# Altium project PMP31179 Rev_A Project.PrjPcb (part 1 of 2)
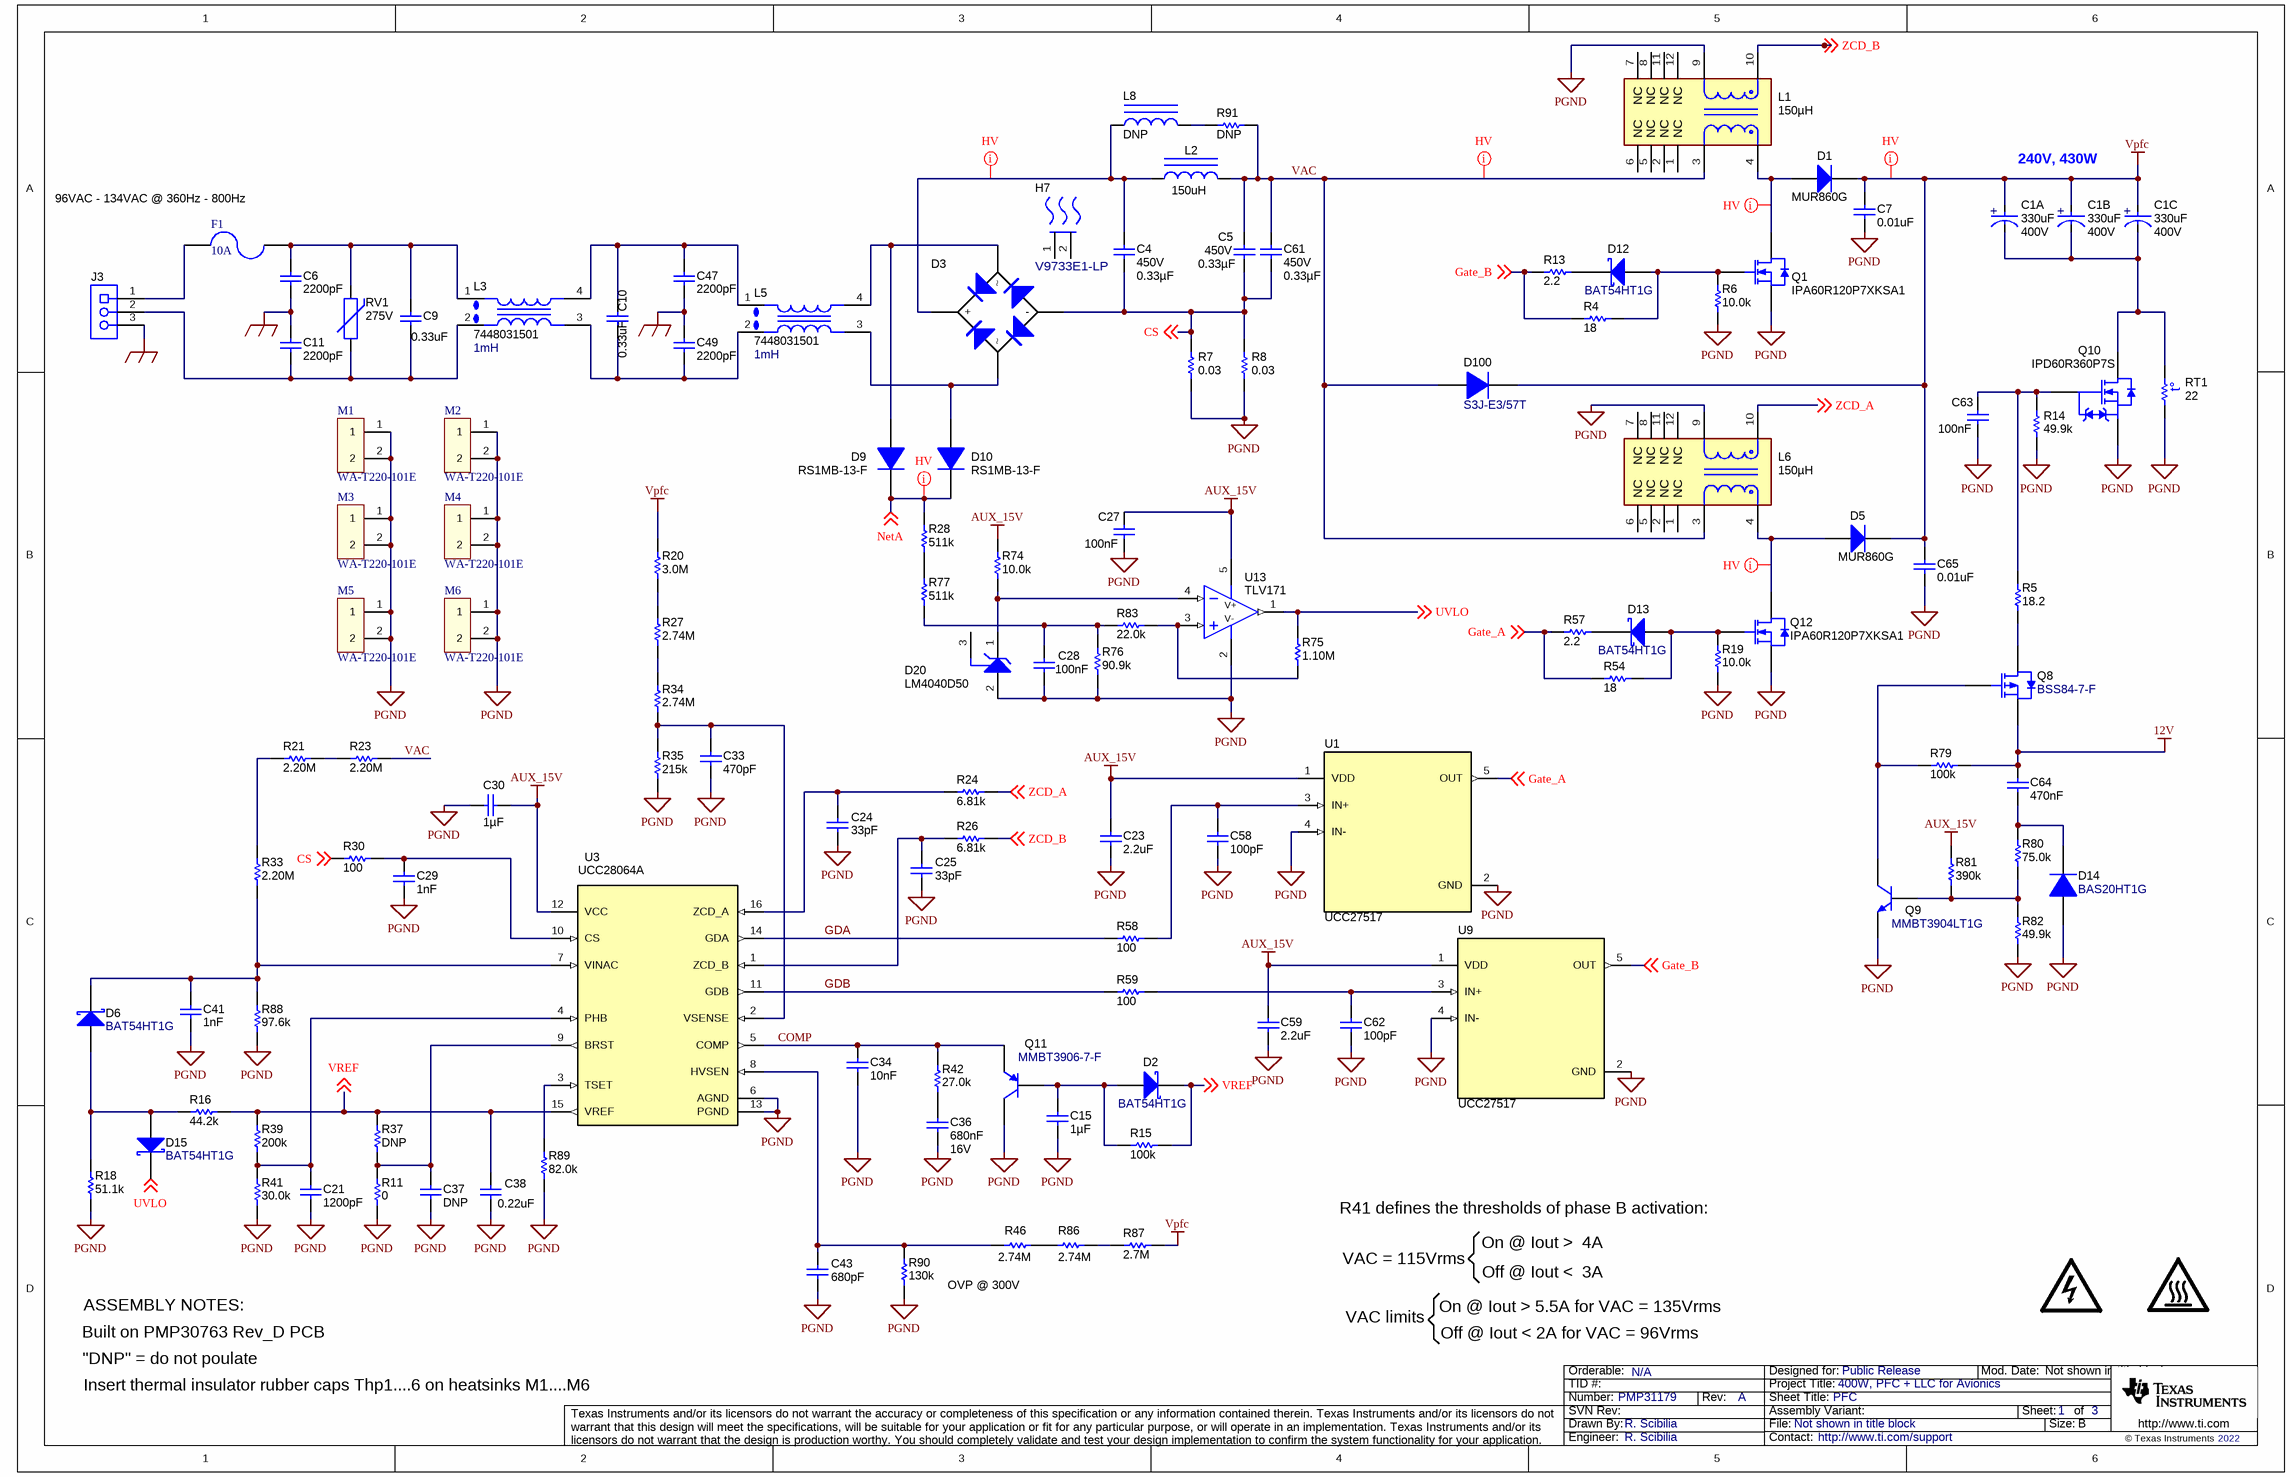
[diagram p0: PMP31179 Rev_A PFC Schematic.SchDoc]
TechSupport: http://www.ti.com/support; SCH_Rev: A; PRJ_Title: 400W, PFC + LLC for Avionics; PRJ_Number: PMP31179; PRJ_Engineer: R. Scibilia; PRJ_Customer: Public Release; PCB_Rev: D; PCB_Layout: PMP30763; EVM_orderable: N/A; CopyrightYear: 2022
3 sheets, 259 parts. Net scope: global (net labels, ports and power ports of the same name join across sheets).
Board file: PMP31179 Rev_A_board.PcbDoc
Sheets:
  PMP31179 Rev_A PFC Schematic.SchDoc
  PMP31179 Rev_A LLC Schematic.SchDoc
  PMP31179 Rev_A Hardware.SchDoc

## Sheet PMP31179 Rev_A PFC Schematic.SchDoc: PFC
size 431 x 279 mm; Date: Not shown in title block; ApprovedBy: Not shown in title block; CheckedBy: Not shown in title block; Author: Not shown in title block; CompanyName: Not shown in title block; DrawnBy: R. Scibilia; Engineer: R. Scibilia; Organization: Not shown in title block; Address1: Not shown in title block; Address2: Not shown in title block; Address3: Not shown in title block; Address4: Not shown in title block; DocumentNumber: 1; Revision: Use project parameter SCH_Rev; SheetNumber: 1; SheetTotal: 3; PageSetup: Record=PageOptions¦CenterHorizontal=True¦CenterVertical=True¦PrintScale=1.00¦XCorrection=1.00¦YCorrection=1.00¦PrintKind=0¦BorderSize=5000000¦LeftOffset=0¦BottomOffset=0¦Orientation=2¦PaperLength=1000¦PaperWidth=1000¦Scale=100¦PaperSource=15¦PrintQuality=600¦MediaType=1¦DitherType=10¦PaperKind=Letter¦PrintScaleMode=1

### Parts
(Parts that share a designator on the sheet are numbered #1, #2 ... from top to bottom, then left to right.)
C1A  VDC_V: 400V  ValueDisplayed: 330uF  [FP-ESMR451VSN221MR25S_RADIAL-MFG]  (hidden comment: 861011385023)
C1B  VDC_V: 400V  ValueDisplayed: 330uF  [FP-ESMR451VSN221MR25S_RADIAL-MFG]  (hidden comment: 861011385023)
C1C  VDC_V: 400V  ValueDisplayed: 330uF  [FP-ESMR451VSN221MR25S_RADIAL-MFG]  (hidden comment: 861011385023)
C4  VDC_V: 450V  ValueDisplayed: 0.33µF  [R46_1300x1200x600]  (hidden comment: ECW-FE2W334K)
C5  VDC_V: 450V  ValueDisplayed: 0.33µF  [R46_1300x1200x600]  (hidden comment: ECW-FE2W334K)
C6  ValueDisplayed: 2200pF  [AY2_950x500_Straight]  (hidden comment: Capacitor)
C7  ValueDisplayed: 0.01uF  [1210]  (hidden comment: 885342208009)
C9  ValueDisplayed: 0.33uF  [B32922_14.5mm]  (hidden comment: Capacitor)
C10  ValueDisplayed: 0.33uF  [B32922_14.5mm]  (hidden comment: Capacitor)
C11  ValueDisplayed: 2200pF  [AY2_950x500_Straight]  (hidden comment: Capacitor)
C15  Cap_F: 1µF  [0603]  (hidden comment: 885012206076)
C21  value 1200pF  [0603]  (hidden comment: GRM1885C1H122JA01D)
C23  value 2.2uF  [0805_150]  (hidden comment: 885012207079)
C24  ValueDisplayed: 33pF  [0603]  (hidden comment: 885012006054)
C25  ValueDisplayed: 33pF  [0603]  (hidden comment: 885012006054)
C27  Cap_F: 100nF  [0603]  (hidden comment: 885012206095)
C28  Cap_F: 100nF  [0603]  (hidden comment: 885012206095)
C29  Cap_F: 1nF  [0603]  (hidden comment: 885012206083)
C30  Cap_F: 1µF  [0603]  (hidden comment: 885012206076)
C33  ValueDisplayed: 470pF  [0603]  (hidden comment: 885012006061)
C34  Cap_F: 10nF  [0603]  (hidden comment: 885012206040)
C36  Cap_F: 680nF  VDC_V: 16V  [0603]  (hidden comment: CL10B684KO8NFNC)
C37  DNP  [0603]
C38  ValueDisplayed: 0.22uF  [0603]  (hidden comment: GRM188R71H224KAC4D)
C41  Cap_F: 1nF  [0603]  (hidden comment: 885012206108)
C43  ValueDisplayed: 680pF  [0603]  (hidden comment: Capacitor)
C47  ValueDisplayed: 2200pF  [AY2_950x500_Straight]  (hidden comment: Capacitor)
C49  ValueDisplayed: 2200pF  [AY2_950x500_Straight]  (hidden comment: Capacitor)
C58  ValueDisplayed: 100pF  [0603]  (hidden comment: 885012006057)
C59  value 2.2uF  [0805_150]  (hidden comment: 885012207079)
C61  VDC_V: 450V  ValueDisplayed: 0.33µF  [R46_1300x1200x600]  (hidden comment: ECW-FE2W334K)
C62  ValueDisplayed: 100pF  [0603]  (hidden comment: 885012006057)
C63  Cap_F: 100nF  [0603]  (hidden comment: 885012206095)
C64  Cap_F: 470nF  [0805_HV]  (hidden comment: 885012207102)
C65  ValueDisplayed: 0.01uF  [1210]  (hidden comment: 885342208009)
D1  MUR860G  [TO-220AC]
D2  BAT54HT1G  [SOD-323]
D3  GBU2510-G  [GBU]  (value not drawn)
D5  MUR860G  [TO-220AC]
D6  BAT54HT1G  [SOD-323]
D9  Value1: RS1MB-13-F  [SMB]  (hidden comment: DIODE)
D10  Value1: RS1MB-13-F  [SMB]  (hidden comment: DIODE)
D12  BAT54HT1G  [SOD-323]
D13  BAT54HT1G  [SOD-323]
D14  BAS20HT1G  [SOD-323]
D15  BAT54HT1G  [SOD-323]
D20  value LM4040D50  [DBZ0003A_N]  (hidden comment: LM4040D50QDBZR)
D100  S3J-E3/57T  [SMC]
F1  value 10A  [FUSE_38321000000]  (hidden comment: 38321000000)
H7  V9733E1-LP  [FP-V9733E1-LP_THERMAL_HEATSINK_25MM0_42MM0-MFG]
J3  691213510003  [On-Shore_ED120_3DS]  (value not drawn)
L1  value 150µH  [FP-750318973r00_PTH_30MM35_29MM2-MFG]  (hidden comment: 750318973r00)
L2  ValueDisplayed: 150uH  [WE-FI_2750x1300]  (hidden comment: 7447076)
L3  7448031501  value 1mH  [WURTH_7448031501]
L5  7448031501  value 1mH  [WURTH_7448031501]
L6  value 150µH  [FP-750318973r00_PTH_30MM35_29MM2-MFG]  (hidden comment: 750318973r00)
L8  DNP  [WE-PD4-S]
LOGO?#1  DANGER HIGH VOLTAGE  [IEC_HighVoltage_Small]  (value not drawn)  (graphical)
LOGO?#2  CAUTION HOT SURFACE  [IEC_HotSurface_Small]  (value not drawn)  (graphical)
M1  WA-T220-101E  [HEATSINK_WA-T220-101E]
M2  WA-T220-101E  [HEATSINK_WA-T220-101E]
M3  WA-T220-101E  [HEATSINK_WA-T220-101E]
M4  WA-T220-101E  [HEATSINK_WA-T220-101E]
M5  WA-T220-101E  [HEATSINK_WA-T220-101E]
M6  WA-T220-101E  [HEATSINK_WA-T220-101E]
Q1  IPA60R120P7XKSA1  [TO-220AB]
Q8  BSS84-7-F  [SOT-23]
Q9  MMBT3904LT1G  [SOT-23]
Q10  value IPD60R360P7S  [DPAK]  (hidden comment: IPD60R360P7SAUMA1)
Q11  MMBT3906-7-F  [SOT-23]
Q12  IPA60R120P7XKSA1  [TO-220AB]
R4  ValueDisplayed: 18  [0805_HV]  (hidden comment: ERJ-6GEYJ180V)
R5  ValueDisplayed: 18.2  [0805_HV1]  (hidden comment: Resistor)
R6  ValueDisplayed: 10.0k  [0805_HV]  (hidden comment: Resistor)
R7  ValueDisplayed: 0.03  [2512]  (hidden comment: Resistor)
R8  ValueDisplayed: 0.03  [2512]  (hidden comment: Resistor)
R11  ValueDisplayed: 0  [0603]  (hidden comment: RMCF0603ZT0R00)
R13  ValueDisplayed: 2.2  [0805_HV]  (hidden comment: RC0805JR-072R2L)
R14  ValueDisplayed: 49.9k  [0603]  (hidden comment: ERJ-3EKF4992V)
R15  ValueDisplayed: 100k  [0603]  (hidden comment: CRCW0603100KFKEA)
R16  ValueDisplayed: 44.2k  [0603]  (hidden comment: RC0603FR-0744K2L)
R18  ValueDisplayed: 51.1k  [0603]  (hidden comment: CRCW060351K1FKEA)
R19  ValueDisplayed: 10.0k  [0805_HV]  (hidden comment: Resistor)
R20  ValueDisplayed: 3.0M  [1206]  (hidden comment: CRCW12063M00JNEA)
R21  ValueDisplayed: 2.20M  [0805_HV]  (hidden comment: RC0805FR-072M2L)
R23  ValueDisplayed: 2.20M  [0805_HV]  (hidden comment: RC0805FR-072M2L)
R24  ValueDisplayed: 6.81k  [0603]  (hidden comment: CRCW06036K81FKEA)
R26  ValueDisplayed: 6.81k  [0603]  (hidden comment: CRCW06036K81FKEA)
R27  ValueDisplayed: 2.74M  [0805_HV]  (hidden comment: Resistor)
R28  value 511k  [1206]  (hidden comment: Resistor)
R30  ValueDisplayed: 100  [0603]  (hidden comment: Resistor)
R33  ValueDisplayed: 2.20M  [0805_HV]  (hidden comment: RC0805FR-072M2L)
R34  ValueDisplayed: 2.74M  [0805_HV]  (hidden comment: Resistor)
R35  ValueDisplayed: 215k  [0603]  (hidden comment: RT0603DRE07215KL)
R37  DNP  [0603]
R39  ValueDisplayed: 200k  [0603]  (hidden comment: RC0603FR-07200KL)
R41  ValueDisplayed: 30.0k  [0603]  (hidden comment: ERJ-3EKF3002V)
R42  ValueDisplayed: 27.0k  [0603]  (hidden comment: RC0603FR-0727KL)
R46  ValueDisplayed: 2.74M  [0805_HV]  (hidden comment: Resistor)
R54  ValueDisplayed: 18  [0805_HV]  (hidden comment: ERJ-6GEYJ180V)
R57  ValueDisplayed: 2.2  [0805_HV]  (hidden comment: RC0805JR-072R2L)
R58  ValueDisplayed: 100  [0603]  (hidden comment: ERJ-3EKF1000V)
R59  ValueDisplayed: 100  [0603]  (hidden comment: ERJ-3EKF1000V)
R74  ValueDisplayed: 10.0k  [0805_HV]  (hidden comment: Resistor)
R75  ValueDisplayed: 1.10M  [0603]  (hidden comment: CRCW06031M10FKEA)
R76  ValueDisplayed: 90.9k  [0603]  (hidden comment: CRCW060390K9FKEA)
R77  value 511k  [1206]  (hidden comment: Resistor)
R79  ValueDisplayed: 100k  [0603]  (hidden comment: CRCW0603100KFKEA)
R80  ValueDisplayed: 75.0k  [0603]  (hidden comment: RC0603FR-0775KL)
R81  ValueDisplayed: 390k  [0603]  (hidden comment: CRCW0603390KJNEA)
R82  ValueDisplayed: 49.9k  [0603]  (hidden comment: RC0603FR-0749K9L)
R83  ValueDisplayed: 22.0k  [0603]  (hidden comment: ERJ-3EKF2202V)
R86  ValueDisplayed: 2.74M  [0805_HV]  (hidden comment: Resistor)
R87  ValueDisplayed: 2.7M  [1206]  (hidden comment: CRCW12062M70JNEA)
R88  ValueDisplayed: 97.6k  [0603]  (hidden comment: CRCW060397K6FKEA)
R89  ValueDisplayed: 82.0k  [0603]  (hidden comment: RC0603FR-0782KL)
R90  ValueDisplayed: 130k  [0603]  (hidden comment: CRCW0603130KFKEA)
R91  DNP  [2512]
RT1  value 22  [S237]  (hidden comment: B57237S0220M000)
RV1  value 275V  [VAR_S10K275E2]  (hidden comment: Varistor_MetalOxide)
U1  value UCC27517  [DBV0005A_N]  (hidden comment: UCC27517DBVR)
U3  value UCC28064A  [D0016A_N]  (hidden comment: UCC28064ADR)
U9  value UCC27517  [DBV0005A_N]  (hidden comment: UCC27517DBVR)
U13  value TLV171  [DBV0005A_N]  (hidden comment: TLV171IDBVR)

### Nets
12V: C64.1 Q8.2(S) R79.1
AUX_15V: C23.1 C27.1 C30.1 C59.1 R74.2 R81.2 U1.1(VDD) U3.12(VCC) U9.1(VDD) U13.5(V+)
EARTH: C6.2 C11.1 C47.2 C49.1 J3.3
PGND: C7.2 C15.2 C21.2 C23.2 C24.2 C25.2 C27.2 C28.2 C29.2 C30.2 C33.2 C34.2 C36.2 C37.2 C38.2 C41.2 C43.2 C58.2 C59.2 C62.2 C63.2 C65.2 D14.2(A) D20.2(ANODE) L1.9 L6.9 M1.1 M1.2 M2.1 M2.2 M3.1 M3.2 M4.1 M4.2 M5.1 M5.2 M6.1 M6.2 Q1.3(S) Q9.2(E) Q10.3(S) Q11.3(C) Q12.3(S) R6.1 R7.1 R8.1 R11.1 R14.2 R18.1 R19.1 R35.1 R41.1 R76.1 R82.1 R88.2 R89.1 R90.1 RT1.1 U1.2(GND) U1.4(IN-) U3.6(AGND) U3.13(PGND) U9.2(GND) U9.4(IN-) U13.2(V-)
Vpfc: C1A.2(ANODE) C1B.2(ANODE) C1C.2(ANODE) C7.1 C65.1 D1.1(K) D5.1(K) D100.1(K) R20.2 R87.2
COMP: C34.1 Q11.2(E) R42.1 U3.5(COMP)
CS: C4.2 C5.2 C61.2 D3.4(-) R7.2 R8.2 R30.1 ; off-sheet CS
Gate_A: R54.1 R57.1 U1.5(OUT) ; off-sheet Gate_A
Gate_B: R4.1 R13.1 U9.5(OUT) ; off-sheet Gate_B
GDA: R58.1 U3.14(GDA)
GDB: R59.2 U3.11(GDB)
NetA: D9.1(K) D10.1(K) R28.1 ; off-sheet NetA
UVLO: D15.1(K) R75.2 U13.1(OUT) ; off-sheet UVLO
VAC: C5.1 C61.1 D100.2(A) L1.3 L2.2 L6.3 R23.2 R91.2
VREF: C38.1 D2.1(K) R15.1 R16.2 R37.2 R39.2 U3.15(VREF) ; off-sheet VREF
ZCD_A: L6.10 R24.2 ; off-sheet ZCD_A
ZCD_B: L1.10 R26.2 ; off-sheet ZCD_B
NetC1A_1: C1A.1(CATHODE) C1B.1(CATHODE) C1C.1(CATHODE) Q10.2(D) RT1.2
NetC4_1: C4.1 D3.1(+) L2.1 L8.1
NetC6_1: C6.1 C9.1 F1.2 L3.1 RV1.2
NetC9_2: C9.2 C11.2 J3.2 L3.2 RV1.1
NetC10_1: C10.1 C47.1 L3.4 L5.1
NetC10_2: C10.2 C49.2 L3.3 L5.2
NetC15_1: C15.1 D2.2(A) Q11.1(B) R15.2
NetC21_1: C21.1 R39.1 R41.2 U3.4(PHB)
NetC24_1: C24.1 R24.1 U3.16(ZCD_A)
NetC25_1: C25.1 R26.1 U3.1(ZCD_B)
NetC28_1: C28.1 R76.2 R77.2 R83.1
NetC29_1: C29.1 R30.2 U3.10(CS)
NetC33_1: C33.1 R34.1 R35.2 U3.2(VSENSE)
NetC36_1: C36.1 R42.2
NetC37_1: C37.1 R11.2 R37.1 U3.9(BRST)
NetC41_1: C41.1 D6.1(K) R33.2 R88.1 U3.7(VINAC)
NetC43_1: C43.1 R46.1 R90.2 U3.8(HVSEN)
NetC58_1: C58.1 R58.2 U1.3(IN+)
NetC62_1: C62.1 R59.1 U9.3(IN+)
NetC63_1: C63.1 Q10.1(G) R5.1 R14.1
NetC64_2: C64.2 D14.1(K) R80.2
NetD1_3: D1.3(A) L1.4 Q1.2(D)
NetD3_2: D3.2 D9.2(A) L5.4
NetD3_3: D3.3 D10.2(A) L5.3
NetD5_3: D5.3(A) L6.4 Q12.2(D)
NetD6_2: D6.2(A) D15.2(A) R16.1 R18.2
NetD12_1: D12.1(K) R13.2
NetD12_2: D12.2(A) Q1.1(G) R4.2 R6.2
NetD13_1: D13.1(K) R57.2
NetD13_2: D13.2(A) Q12.1(G) R19.2 R54.2
NetD20_1: D20.1(CATHODE) R74.1 U13.4(IN-)
NetF1_1: F1.1 J3.1
NetL8_2: L8.2 R91.1
NetQ8_1: Q8.1(G) Q9.3(C) R79.2
NetQ8_3: Q8.3(D) R5.2
NetQ9_1: Q9.1(B) R80.1 R81.1 R82.2
NetR20_1: R20.1 R27.2
NetR21_1: R21.1 R33.1
NetR21_2: R21.2 R23.1
NetR27_1: R27.1 R34.2
NetR28_2: R28.2 R77.1
NetR46_2: R46.2 R86.1
NetR75_1: R75.1 R83.2 U13.3(IN+)
NetR86_2: R86.2 R87.1
NetR89_2: R89.2 U3.3(TSET)

Not connected (* = marked no-connect by the designer): D20 3(NC); H7 1(MNT_1) 2(MNT_2); L1 1(NC) 2(NC) 5(NC) 6(NC) 7(NC) 8(NC) 11(NC) 12(NC); L6 1(NC) 2(NC) 5(NC) 6(NC) 7(NC) 8(NC) 11(NC) 12(NC)

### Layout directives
net class HV: NetA, NetC4_1, NetD1_3, NetD5_3, VAC, Vpfc

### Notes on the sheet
- 240V, 430W
- (near F1) 96VAC - 134VAC @ 360Hz - 800Hz
- R41 defines the thresholds of phase B activation:
- OVP @ 300V
- VAC = 115Vrms
- On @ Iout >  4A
- Off @ Iout <  3A
- ASSEMBLY NOTES:
- "DNP" = do not poulate
- Built on PMP30763 Rev_D PCB
- VAC limits
- Off @ Iout < 2A for VAC = 96Vrms
- On @ Iout > 5.5A for VAC = 135Vrms
- Insert thermal insulator rubber caps Thp1....6 on heatsinks M1....M6

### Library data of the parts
C1A C1B C1C = CMP-in_PMP30763: 330µF 400V Aluminum Electrolytic Capacitors Radial, Can - Snap-In  2000 Hrs @ 85°C; Manufacturer: Wuerth; SizeZ_mm: 30mm; Tolerance_%: 20%; Leakage Current: 920uA; Life: 2000Hours; AEC Qualified: No; IRMS_A: 2A
C4 C5 C61 = CMP-0012558-3: 0.33µF Film Capacitor 450V Polypropylene (PP), Metallized Radial; Manufacturer: Panasonic Electronic Components; TaMin_C: -40°C; Polarized: N; SizeAreaWB_mm2: 120; Value1: Unknown; TaMax_C: 110°C; Tolerance_%: 10%; SizeZ_mm: 12.1; SizeX_mm: 13; SizeY_mm: 6; Cap_Case: 13x12x6; SizeArea_mm2: 78; AEC Category: Q200
C6 C11 C47 C49 = CMP-0009587-2: CAP, CERM, 2200 pF, 300 V, +/- 20%, Y5U, AEC-Q200 Grade 1, D9.5xT5mm; PartNumber: AY2222M35Y5US63L7; Manufacturer: Vishay-Bccomponents; Polarized: N; Value: 2200pF; U/M: EA; Cap_F: 2.2nF; Value1: Unknown; VDC_V: 300V; TaMin_C: -55°C; TaMax_C: 125°C; Cap_Case: 9.5x5mm; SizeArea_mm2: 47.5; SizeAreaWB_mm2: 80.5; SizeX_mm: 9.5; SizeY_mm: 5; SizeZ_mm: 14.5; AEC Category: Q200; AEC Qualified: Y; AEC Grade: 1
C7 C65 = CMP-0009273-2: CAP, CERM, 0.01 uF, 500 V, +/- 10%, X7R, 1206; Manufacturer: Wuerth; TaMin_C: -55°C; Polarized: N; SizeAreaWB_mm2: 14.7; Value1: Unknown; U/M: EA; Value: 0.01uF; TaMax_C: 125°C; SizeZ_mm: 1.35; SizeX_mm: 3.2; SizeY_mm: 2.5; Cap_Case: 1206; Value2: 500V; SizeArea_mm2: 8; Cap_F: 10nF; AEC Category: Q200
C9 C10 = CMP-0012409-3: CAP, Film, 0.33 uF, 630 V, +/- 10%, TH; PartNumber: B32922C3334K; Manufacturer: TDK; Polarized: N; Value: 0.33uF; Cap_F: 330nF; Value1: Unknown; VDC_V: 630V; TaMin_C: -40°C; TaMax_C: 110°C; Cap_Case: 18x8x14.5mm; SizeAreaWB_mm2: 210; SizeArea_mm2: 153; SizeX_mm: 18; SizeY_mm: 8.5; SizeZ_mm: 14.5; AEC Category: Q200
C15 C30 = CMP-0006833-4: CAP, CERM, 1 uF, 25 V, +/- 10%, X7R, 0603; Manufacturer: Wurth Elektronik; TaMin_C: -55°C; Polarized: N; SizeAreaWB_mm2: 4.68; Value1: Unknown; U/M: EA; Value: 1uF; TaMax_C: 125°C; SizeZ_mm: 1; SizeX_mm: 1.6; SizeY_mm: 0.8; Value2: 25V; SizeArea_mm2: 1.28; AEC Category: Q200
C21 = CMP-0007180-4: CAP, CERM, 1200 pF, 50 V, +/- 5%, C0G/NP0, 0603; Manufacturer: MuRata; TaMin_C: -55°C; Polarized: N; SizeAreaWB_mm2: 4.68; Value1: Unknown; U/M: EA; TaMax_C: 125°C; SizeZ_mm: 1; SizeX_mm: 1.6; SizeY_mm: 0.8; Value2: 50V; SizeArea_mm2: 1.28; Cap_F: 1.2nF; AEC Category: Q200
C23 C59 = CMP-0007573-2: CAP, CERM, 2.2 uF, 25 V, +/- 10%, X7R, 0805; Manufacturer: Wuerth; TaMin_C: -55°C; Polarized: N; SizeAreaWB_mm2: 6.75; Value1: Unknown; U/M: EA; TaMax_C: 125°C; SizeZ_mm: 1.5; SizeX_mm: 2; SizeY_mm: 1.25; Cap_Case: 0805; Value2: 25V; SizeArea_mm2: 2.5; Cap_F: 2.2µF; AEC Category: Q200
C24 C25 = CMP-0006919-4: CAP, CERM, 33 pF, 50 V, +/- 5%, C0G/NP0, 0603; Manufacturer: Wuerth; TaMin_C: -55°C; Polarized: N; SizeAreaWB_mm2: 4.68; Value1: Unknown; U/M: EA; Value: 33pF; TaMax_C: 125°C; SizeZ_mm: 1; SizeX_mm: 1.6; SizeY_mm: 0.8; Value2: 50V; SizeArea_mm2: 1.28; AEC Category: Q200
C27 C28 C63 = CMP-0006837-3: CAP, CERM, 0.1 uF, 50 V, +/- 10%, X7R, 0603; Manufacturer: Wurth Elektronik; TaMin_C: -55°C; Polarized: N; SizeAreaWB_mm2: 4.68; Value1: Unknown; U/M: EA; Value: 0.1uF; TaMax_C: 125°C; SizeZ_mm: 1; SizeX_mm: 1.6; SizeY_mm: 0.8; Value2: 50V; SizeArea_mm2: 1.28; AEC Category: Q200
C29 = CMP-0064933-4: CAP, CERM, 1000 pF, 50 V,+/- 10%, X7R, 0603; Manufacturer: Wurth Elektronik; TaMin_C: -55°C; Polarized: N; SizeAreaWB_mm2: 4.68; Value1: Unknown; U/M: EA; Value: 1000pF; TaMax_C: 125°C; SizeZ_mm: 1; SizeX_mm: 1.6; SizeY_mm: 0.8; Value2: 50V; SizeArea_mm2: 1.28; AEC Category: Q200
C33 = CMP-0007221-4: CAP, CERM, 470 pF, 50 V, +/- 5%, C0G/NP0, 0603; Manufacturer: Wuerth; TaMin_C: -55°C; Polarized: N; SizeAreaWB_mm2: 4.68; Value1: Unknown; U/M: EA; Value: 470pF; TaMax_C: 125°C; SizeZ_mm: 1; SizeX_mm: 1.6; SizeY_mm: 0.8; Value2: 50V; SizeArea_mm2: 1.28; AEC Category: Q200
C34 = CMP-0006828-3: CAP, CERM, 0.01 uF, 16 V, +/- 10%, X7R, 0603; Manufacturer: Wurth Elektronik; TaMin_C: -55°C; Polarized: N; SizeAreaWB_mm2: 4.68; Value1: Unknown; U/M: EA; Value: 0.01uF; TaMax_C: 125°C; SizeZ_mm: 1; SizeX_mm: 1.6; SizeY_mm: 0.8; Value2: 16V; SizeArea_mm2: 1.28; AEC Category: Q200
C36 = CMP-0007375-4: CAP, CERM, 0.68 uF, 16 V, +/- 10%, X7R, 0603; Manufacturer: Samsung; TaMin_C: -55°C; Polarized: N; SizeAreaWB_mm2: 4.68; Value1: Unknown; U/M: EA; Value: 0.68uF; TaMax_C: 125°C; SizeZ_mm: 1; SizeX_mm: 1.6; SizeY_mm: 0.8; SizeArea_mm2: 1.28; AEC Category: Q200
C37 = CMP-0007180-4: TaMin_C: -55°C; Polarized: N; TempCo: C0G/NP0; SizeAreaWB_mm2: 4.68; Value1: Unknown; U/M: EA; TaMax_C: 125°C; Tolerance_%: 5%; SizeZ_mm: 1; SizeX_mm: 1.6; SizeY_mm: 0.8; Value2: 50V; SizeArea_mm2: 1.28; AEC Category: Q200
C38 = CMP-0007445-4: CAP, CERM, 0.22 uF, 50 V, +/- 10%, X7R, 0603; Manufacturer: MuRata; TaMin_C: -55°C; Polarized: N; SizeAreaWB_mm2: 4.68; Value1: Unknown; U/M: EA; Value: 0.22uF; TaMax_C: 125°C; SizeZ_mm: 1; SizeX_mm: 1.6; SizeY_mm: 0.8; Value2: 50V; SizeArea_mm2: 1.28; CompType: Capacitor; Cap_F: 220nF; AEC Category: Q200
C41 = CMP-0007053-4: CAP, CERM, 1000 pF, 100 V, +/- 10%, X7R, 0603; Manufacturer: Wuerth; TaMin_C: -55°C; Polarized: N; SizeAreaWB_mm2: 4.68; Value1: Unknown; U/M: EA; Value: 1000pF; TaMax_C: 125°C; SizeZ_mm: 1; SizeX_mm: 1.6; SizeY_mm: 0.8; Value2: 100V; SizeArea_mm2: 1.28; AEC Category: Q200
C43 = CMP-0007461-4: CAP, CERM, 680 pF, 50 V, +/- 10%, X7R, 0603; PartNumber: 885012206082; Manufacturer: Wuerth; Polarized: N; Value: 680pF; U/M: EA; Value1: Unknown; VDC_V: 50V; TaMin_C: -55°C; TaMax_C: 125°C; AEC Category: Q200; SizeArea_mm2: 1.28; SizeAreaWB_mm2: 4.68; SizeX_mm: 1.6; SizeY_mm: 0.8; SizeZ_mm: 1
C58 C62 = CMP-0006822-4: CAP, CERM, 100 pF, 50 V, +/- 5%, C0G/NP0, 0603; Manufacturer: Wurth Elektronik; TaMin_C: -55°C; Polarized: N; SizeAreaWB_mm2: 4.68; Value1: Unknown; U/M: EA; Value: 100pF; TaMax_C: 125°C; SizeZ_mm: 1; SizeX_mm: 1.6; SizeY_mm: 0.8; Value2: 50V; SizeArea_mm2: 1.28; AEC Category: Q200
C64 = CMP-0007695-2: CAP, CERM, 0.47 uF, 50 V, +/- 10%, X7R, 0805; Manufacturer: Wurth Elektronik; TaMin_C: -55°C; Polarized: N; SizeAreaWB_mm2: 6.75; Value1: Unknown; U/M: EA; Value: 0.47uF; TaMax_C: 125°C; SizeZ_mm: 1.45; SizeX_mm: 2; SizeY_mm: 1.25; Cap_Case: 0805; Value2: 50V; SizeArea_mm2: 2.5; AEC Category: Q200
D1 D5 = CMP-0029037-2: Diode, Ultrafast, 600 V, 8 A, TH; Manufacturer: ON Semiconductor; Io_A: 8A; Green_Lifecycle: Not Set; SizeAreaWB_mm2: 78.975; Vr_V: 600V; Green_REACh: Incomplete; TJmax_C: 175°C; SizeZ_mm: 23; SizeX_mm: 10.15; SizeY_mm: 4.5; Vf_V: 980mV; Value2: 0.98V; SizeArea_mm2: 45.675; AEC Category: Q101; RJC_CperW: 4.75
D2 D6 D12 D13 D15 = CMP-0028455-2: Diode, Schottky, 30 V, 0.2 A, SOD-323; Manufacturer: ON Semiconductor; Vr_V: 30V; SizeZ_mm: 1; Value1: 0.2A; SizeAreaWB_mm2: 8.695; Vf_V: 350mV; Io_A: 200mA; SizeX_mm: 2.7; SizeY_mm: 1.35; Green_Lifecycle: Active; AEC Category: Q101; Value2: 0.35V; SizeArea_mm2: 3.645; Green_REACh: Passed
D3 = GBU4A-BP: RECT BRIDGE GPP 1000V 25A GBU; Manufacturer: Comchip Technology; CompType: Diode; U/M: EA; Vf_V: 0.95; Io_A: 4; Value1: 8A; Vr_V: 50; Value2: 50V; TJmax_C: 150; RJC_CperW: 2.2; Type: Switching-Bridge
D9 D10 = CMP-0076889-2: Diode, P-N, 1000 V, 1 A, SMB; Manufacturer: Diodes Inc.; Vf_V: 1.3V; Value: RS1MB-13-F; Io_A: 1A; Vr_V: 1kV; TJmax_C: 150°C; RJC_CperW: 20.0; SizeAreaWB_mm2: 44.156; SizeArea_mm2: 21.336; SizeX_mm: 5.6; SizeY_mm: 3.81; SizeZ_mm: 2.6; AEC Category: Q101; Green_Lifecycle: Active; Green_REACh: Passed
D14 = CMP-0029150-2: Diode, Switching, 200 V, 0.2 A, AEC-Q101, SOD-323; Manufacturer: ON Semiconductor; Value2: 1.25V; Value1: 0.2A; SizeZ_mm: 1; Green_REACh: Incomplete; SizeArea_mm2: 3.645; Vr_V: 200V; SizeX_mm: 2.7; TJmax_C: 150°C; Io_A: 200mA; Green_Lifecycle: Not Set; SizeAreaWB_mm2: 8.695; AEC Qualified: Y; AEC Category: Q101; SizeY_mm: 1.35
D20 = CMP-0033016-1: Precision Micropower Shunt Voltage Reference, 1% accuracy, 5 V, 15 ppm / degC, 15 mA, -40 to 125 degC, 3-pin SOT-23 (DBZ), Green (RoHS & no Sb/Br); Manufacturer: Texas Instruments; Rating: Catalog; Temp Coeff(Typ)(ppm/ degree C): 15; Initial Accuracy @ 25/deg C(%): 1; Temp Coeff(Max)(ppm/ degree C): 150; VO(V): 5; Min Iz for Regulation(uA): 79
D100 = CMP-0082070-2: Diode, Switching, 600 V, 3 A, SMC; Manufacturer: Vishay-Semiconductor; SizeArea_mm2: 50.5686; Value2: 1.15V; RJC_CperW: 13; SizeY_mm: 6.22; TJmax_C: 150°C; SizeAreaWB_mm2: 83.2686; Io_A: 3A; AEC Category: Q101; SizeZ_mm: 2.62; Vr_V: 600V; AEC Qualified: N; SizeX_mm: 8.13
F1 = 38321000000: FUSE, BOARD MOUNT, 10 A, 300 V, TH-2P; Manufacturer: LITTELFUSE INC; SymbolCreator: x0199378
H7 = CMP-0092962-1: Heat Sink 11 K/W, 25,4x42x25 mm, black anodized, for TO-220; Manufacturer: Assmann WSW components; SizeZ_mm: 25.4mm; Thermal Resistance Forced Air Flow: 11°C/W; AEC Qualified: No
J3 = CMP-0074911-1: Terminal Block, 5.08 mm, 3x1, Brass, TH; Manufacturer: Wuerth; Cert_VDE: Y; CNHeader: False; Current_A: 14A; Green_Lifecycle: Not Set; Shrouded: N; Gender: Female; Green_REACh: Incomplete; Voltage_V: 300V; Row_Count: 1; Pitch_mm: 5.08; CT: True
L1 L6 = CMP-0088743-1: INDUCTOR; Manufacturer: Wurth Electronics; AEC Qualified: No; Voltage_Isolation_Vrms: 1kV; Rsec1_ohm: 44m; Ns1toNp: 16.5:1; SizeZ_mm: 29.3mm; DCR_ohm: 50m
L2 = CMP-0064735-2: Inductor, Toroid, Powdered Iron, 150 uH, 5 A, 0.045 ohm, TH; Manufacturer: Wurth Elektronik; Value: 150uH; Ind_H: 150µH; Imax_A: 5A; Irms: 5A @ 40C rise; DCR_ohm: 45m; AEC Category: Q200; AEC Qualified: N; Green_Lifecycle: Active; Green_REACh: Passed; SizeArea_mm2: 357.5; SizeAreaWB_mm2: 442.5; SizeX_mm: 13; SizeY_mm: 27.5
L3 L5 = 7448031501: FILTER, WE-CMBNC COMMON MODE POWER LINE CHOKE, 1mH, 15A, VERTICAL, TH-4P; Manufacturer: Wurth Elektronics; SymbolCreator: x0199378
L8 = CMP-0064496-2: Manufacturer: Wurth Elektronik; Isat: 0.7A @ 10% inductance drop; Green_Lifecycle: Active; SizeAreaWB_mm2: 55.47; DCR_ohm: 0.255; Green_REACh: Passed; Material: Ferrite; SizeZ_mm: 2.92; SizeX_mm: 6.6; SizeY_mm: 4.45; SizeArea_mm2: 29.37; CompType: Inductor; AEC Category: Q200
LOGO?#1 = IEC_HighVoltage: IEC 61010-1 High Voltage Warning; SymbolCreator: a0412235
LOGO?#2 = IEC_HotSurface: IEC 61010-1 Hot Surface Warning; SymbolCreator: a0412235
M1-M6 = WA-T220-101E: HEATSINK, ALUMINIUM WITH CLIP, VERTICAL MOUNT, SOLDERABLE PIN, TO-220; Manufacturer: OHMITE; SymbolCreator: x0199378
Q1 Q12 = CMP-0001223-3: MOSFET N-CHANNEL 600V 26A TO220; Alternate Manufacturer: None; Manufacturer: Infineon Technologies; SizeZ_mm: 19.4; ChType: N; Value2: 37 nC; VdsMax_V: 650V; SizeX_mm: 10.2; SizeY_mm: 4.5; Vgs_V: 20V; QgTyp_nC: 37; SizeArea_mm2: 45.9; AEC Category: Q101; IdsMax_A: 20.2A; SizeAreaWB_mm2: 79.3; U/M: EA
Q8 = CMP-0000011-2: MOSFET, P-CH, -50 V, -0.13 A, SOT-23; Alternate Manufacturer: None; Manufacturer: Diodes Inc.; SizeZ_mm: 1.1; ChType: P; VdsMax_V: -50V; SizeX_mm: 2.5; SizeY_mm: 3; Vgs_V: -20V; AEC Qualified: N; SizeArea_mm2: 7.5; AEC Category: Q101; IdsMax_A: -130mA; SizeAreaWB_mm2: 14; U/M: EA
Q9 = CMP-0000419-1: Transistor, NPN, 40 V, 0.2 A, SOT-23; Manufacturer: ON Semiconductor; TaMax_C: 150°C; Value2: 300; Value1: 0.2 A; Vcesat1_V: 300mV; SizeX_mm: 2.5; SizeY_mm: 3; TaMin_C: -55°C; IcRated_A: 200mA; CompType: BJT; SizeZ_mm: 1.1; SizeArea_mm2: 7.5; NPN: 1; Vceo_V: 40V; PNP: 0; AEC Category: Q101; SizeAreaWB_mm2: 14; U/M: EA
Q10 = CMP-0079555-2: MOSFET, N-CH, 600 V, 9 A, DPAK; Manufacturer: Infineon Technologies; Alternate Manufacturer: None; SizeArea_mm2: 64.8114; Value1: ? ohm; IdsMax_A: 9A; ChType: N; Vgs_V: 20V; SizeX_mm: 9.91; AEC Category: Q101; SizeZ_mm: 2.29; VdsMax_V: 600V; Value2: 13 nC; ChMode: Enhancement; SizeAreaWB_mm2: 101.7114; QgTyp_nC: 13; SizeY_mm: 6.54
Q11 = CMP-0000326-1: Transistor, PNP, 40 V, 0.2 A, SOT-23; Manufacturer: Diodes Inc.; TaMax_C: 150°C; Value2: 400; Value1: 0.2 A; Vcesat1_V: 250mV; SizeX_mm: 2.5; SizeY_mm: 3; TaMin_C: -55°C; IcRated_A: 200mA; CompType: BJT; SizeZ_mm: 1.1; SizeArea_mm2: 7.5; NPN: 0; Vceo_V: 40V; PNP: 1; AEC Category: Q101; SizeAreaWB_mm2: 14; U/M: EA
R4 R54 = CMP-0020655-3: RES, 18, 5%, 0.125 W, AEC-Q200 Grade 0, 0805; Manufacturer: Panasonic; Power_W: 125mW; TempCo: 200 ppm/C; Value_Code: 18R0; Value: 18; EIA_Code: E24; SizeX_mm: 2; SizeY_mm: 1.25; SizeZ_mm: 1.45; Value2: 0.125W; SizeArea_mm2: 2.5; AEC Qualified: Y; VDC_V: 150V; AEC Category: Q200; AEC Grade: 0; SizeAreaWB_mm2: 6.75
R5 = CMP-0020941-3: RES, 18.2, 1%, 0.125 W, AEC-Q200 Grade 0, 0805; PartNumber: CRCW080518R2FKEA; Manufacturer: Vishay-Dale; Value: 18.2; Value_Code: 18R2; Power_W: 125mW; Value2: 0.125W; VDC_V: 150V; TempCo: 100 ppm/C; SizeArea_mm2: 2.5; SizeX_mm: 2; SizeY_mm: 1.25; SizeZ_mm: 1.45; EIA_Code: E96; AEC Category: Q200; AEC Qualified: Y; AEC Grade: 0
R6 R19 R74 = CMP-0020842-3: RES, 10.0 k, 1%, 0.125 W, AEC-Q200 Grade 0, 0805; PartNumber: CRCW080510K0FKEA; Manufacturer: Vishay-Dale; Value: 10.0k; Res_ohm: 10k; Value_Code: 10k0; Power_W: 125mW; Value2: 0.125W; VDC_V: 150V; TempCo: 100 ppm/C; EIA_Code: E96; AEC Category: Q200; AEC Grade: 0; AEC Qualified: Y; SizeArea_mm2: 2.5; SizeX_mm: 2; SizeY_mm: 1.25; SizeZ_mm: 1.45
R7 R8 = CMP-0015775-2: RES, 0.03, 1%, 2 W, 2512; PartNumber: CSRN2512FK30L0; Manufacturer: Stackpole Electronics Inc; Value: 0.03; Res_ohm: 30m; Value_Code: R030; Power_W: 2W; TempCo: 200 ppm/C; SizeArea_mm2: 20.16; SizeX_mm: 6.3; SizeY_mm: 3.2; SizeZ_mm: 0.71; EIA_Code: E96; U/M: EA; AEC Category: Q200
R11 = CMP-0023343-3: RES, 0, 1%, 0.1 W, AEC-Q200 Grade 0, 0603; Manufacturer: Stackpole Electronics Inc; Power_W: 100mW; TempCo: ppm/C; U/M: EA; Value: 0; SizeX_mm: 1.6; SizeY_mm: 0.8; SizeZ_mm: 1; Value2: 0.1W; SizeArea_mm2: 1.28; AEC Qualified: Y; AEC Category: Q200
R13 R57 = CMP-0020812-2: RES, 2.2, 5%, 0.125 W, 0805; Manufacturer: Yageo America; Power_W: 125mW; TempCo: 200 ppm/C; Value_Code: 2R20; U/M: EA; Value: 2.2; EIA_Code: E24; SizeX_mm: 2; SizeY_mm: 1.25; SizeZ_mm: 1.45; Value2: 0.125W; SizeArea_mm2: 2.5; VDC_V: 150V; AEC Category: Q200
R14 = CMP-0022705-3: RES, 49.9 k, 1%, 0.1 W, AEC-Q200 Grade 0, 0603; Manufacturer: Panasonic; Power_W: 100mW; TempCo: 100 ppm/C; Value_Code: 49k9; U/M: EA; Value: 49.9k; EIA_Code: E96; SizeX_mm: 1.6; SizeY_mm: 0.8; SizeZ_mm: 1; Value2: 0.1W; SizeArea_mm2: 1.28; AEC Qualified: Y; VDC_V: 75V; AEC Grade: 0; AEC Category: Q200
R15 R79 = CMP-0021990-4: RES, 100 k, 1%, 0.1 W, AEC-Q200 Grade 0, 0603; Manufacturer: Vishay-Dale; Power_W: 100mW; TempCo: 100 ppm/C; Value: 100k; EIA_Code: E96; SizeX_mm: 1.6; SizeY_mm: 0.8; SizeZ_mm: 1; Value2: 0.1W; SizeArea_mm2: 1.28; AEC Qualified: Y; VDC_V: 75V; AEC Category: Q200; AEC Grade: 0
R16 = CMP-0023118-5: RES, 44.2 k, 1%, 0.1 W, 0603; Manufacturer: Yageo; Power_W: 100mW; TempCo: 100 ppm/C; Value_Code: 44k2; Value: 44.2k; EIA_Code: E96; SizeX_mm: 1.6; SizeY_mm: 0.8; SizeZ_mm: 1; Value2: 0.1W; SizeArea_mm2: 1.28; AEC Qualified: N; VDC_V: 75V; AEC Category: Q200; SizeAreaWB_mm2: 4.68
R18 = CMP-0022482-4: RES, 51.1 k, 1%, 0.1 W, AEC-Q200 Grade 0, 0603; Manufacturer: Vishay-Dale; Power_W: 100mW; TempCo: 100 ppm/C; Value_Code: 51k1; Value: 51.1k; EIA_Code: E96; SizeX_mm: 1.6; SizeY_mm: 0.8; SizeZ_mm: 1; Value2: 0.1W; SizeArea_mm2: 1.28; AEC Qualified: Y; VDC_V: 75V; AEC Category: Q200; AEC Grade: 0
R20 = CMP-0018672-3: RES, 3.0 M, 5%, 0.25 W, AEC-Q200 Grade 0, 1206; Manufacturer: Vishay-Dale; Power_W: 250mW; TempCo: 200 ppm/C; Value_Code: 3M00; Value: 3.0Meg; EIA_Code: E24; Res_ohm: 3M; SizeX_mm: 3.2; SizeY_mm: 1.6; SizeZ_mm: 1.35; Value2: 0.25W; SizeArea_mm2: 5.12; AEC Qualified: Y; VDC_V: 200V; AEC Category: Q200; AEC Grade: 0
R21 R23 R33 = CMP-0021895-2: RES, 2.20 M, 1%, 0.125 W, 0805; Manufacturer: Yageo America; Power_W: 125mW; TempCo: 100 ppm/C; Value_Code: 2M20; U/M: EA; Value: 2.20Meg; Res_ohm: 2.2M; SizeX_mm: 2; SizeY_mm: 1.25; SizeZ_mm: 1.45; Value2: 0.125W; SizeArea_mm2: 2.5; VDC_V: 150V; AEC Category: Q200
R24 R26 = CMP-0022563-4: RES, 6.81 k, 1%, 0.1 W, AEC-Q200 Grade 0, 0603; Manufacturer: Vishay-Dale; Power_W: 100mW; TempCo: 100 ppm/C; Value_Code: 6k81; Value: 6.81k; EIA_Code: E96; SizeX_mm: 1.6; SizeY_mm: 0.8; SizeZ_mm: 1; Value2: 0.1W; SizeArea_mm2: 1.28; AEC Qualified: Y; VDC_V: 75V; AEC Category: Q200; AEC Grade: 0
R27 R34 R46 R86 = CMP-0021137-3: RES, 2.74 M, 1%, 0.125 W, AEC-Q200 Grade 0, 0805; PartNumber: CRCW08052M74FKEA; Manufacturer: Vishay-Dale; Value: 2.74Meg; Value_Code: 2M74; Power_W: 125mW; Value2: 0.125W; VDC_V: 150V; TempCo: 100 ppm/C; EIA_Code: E96; AEC Category: Q200; AEC Grade: 0; AEC Qualified: Y; SizeArea_mm2: 2.5; SizeX_mm: 2; SizeY_mm: 1.25; SizeZ_mm: 1.45
R28 R77 = CMP-0017050-3: RES, 511 k, 1%, 0.25 W, AEC-Q200 Grade 0, 1206; PartNumber: CRCW1206511KFKEA; Manufacturer: Vishay-Dale; Power_W: 250mW; Value2: 0.25W; VDC_V: 200V; TempCo: 100 ppm/C; EIA_Code: E96; AEC Category: Q200; AEC Grade: 0; AEC Qualified: Y; SizeArea_mm2: 5.12; SizeX_mm: 3.2; SizeY_mm: 1.6; SizeZ_mm: 1.35
R30 = CMP-0021991-4: RES, 100, 1%, 0.1 W, AEC-Q200 Grade 0, 0603; PartNumber: CRCW0603100RFKEA; Manufacturer: Vishay-Dale; Value: 100; Value_Code: 100R; Power_W: 100mW; Value2: 0.1W; VDC_V: 75V; TempCo: 100 ppm/C; EIA_Code: E96; AEC Category: Q200; AEC Grade: 0; AEC Qualified: Y; SizeArea_mm2: 1.28; SizeX_mm: 1.6; SizeY_mm: 0.8; SizeZ_mm: 1
R35 = CMP-0024931-3: RES, 215 k, 0.5%, 0.1 W, 0603; Manufacturer: Yageo America; Power_W: 100mW; TempCo: 50 ppm/C; U/M: EA; Value: 215k; EIA_Code: E192; SizeX_mm: 1.6; SizeY_mm: 0.8; SizeZ_mm: 1; Value2: 0.1W; SizeArea_mm2: 1.28; VDC_V: 75V; AEC Category: Q200
R37 = CMP-0022093-4: Power_W: 100mW; TempCo: 100 ppm/C; Value1: 1%; EIA_Code: E96; SizeX_mm: 1.6; SizeY_mm: 0.8; SizeZ_mm: 1; Value2: 0.1W; SizeArea_mm2: 1.28; AEC Qualified: Y; VDC_V: 75V; AEC Category: Q200; AEC Grade: 0
R39 = CMP-0022901-4: RES, 200 k, 1%, 0.1 W, 0603; Manufacturer: Yageo; Power_W: 100mW; TempCo: 100 ppm/C; Value: 200k; EIA_Code: E96; SizeX_mm: 1.6; SizeY_mm: 0.8; SizeZ_mm: 1; Value2: 0.1W; AEC Qualified: N; VDC_V: 75V; AEC Category: Q200; SizeArea_mm2: 1.28; SizeAreaWB_mm2: 4.68
R41 = CMP-0022695-3: RES, 30.0 k, 1%, 0.1 W, AEC-Q200 Grade 0, 0603; Manufacturer: Panasonic; Power_W: 100mW; TempCo: 100 ppm/C; Value_Code: 30k0; U/M: EA; Value: 30.0k; Res_ohm: 30k; SizeX_mm: 1.6; SizeY_mm: 0.8; SizeZ_mm: 1; Value2: 0.1W; SizeArea_mm2: 1.28; AEC Qualified: Y; VDC_V: 75V; AEC Grade: 0; AEC Category: Q200
R42 = CMP-0022966-5: RES, 27.0 k, 1%, 0.1 W, 0603; Manufacturer: Yageo; Power_W: 100mW; TempCo: 100 ppm/C; Value_Code: 27k0; Value: 27.0k; Res_ohm: 27k; SizeX_mm: 1.6; SizeY_mm: 0.8; SizeZ_mm: 1; Value2: 0.1W; SizeArea_mm2: 1.28; AEC Qualified: N; VDC_V: 75V; AEC Category: Q200; SizeAreaWB_mm2: 4.68
R58 R59 = CMP-0022679-3: RES, 100, 1%, 0.1 W, AEC-Q200 Grade 0, 0603; Manufacturer: Panasonic; Power_W: 100mW; TempCo: 100 ppm/C; Value_Code: 100R; U/M: EA; Value: 100; EIA_Code: E96; SizeX_mm: 1.6; SizeY_mm: 0.8; SizeZ_mm: 1; Value2: 0.1W; SizeArea_mm2: 1.28; AEC Qualified: Y; AEC Grade: 0; AEC Category: Q200
R75 = CMP-0022142-4: RES, 1.10 M, 1%, 0.1 W, AEC-Q200 Grade 0, 0603; Manufacturer: Vishay-Dale; Power_W: 100mW; TempCo: 100 ppm/C; Value_Code: 1M10; Value: 1.10Meg; EIA_Code: E96; Res_ohm: 1.1M; SizeX_mm: 1.6; SizeY_mm: 0.8; SizeZ_mm: 1; Value2: 0.1W; SizeArea_mm2: 1.28; AEC Qualified: Y; VDC_V: 75V; AEC Category: Q200; AEC Grade: 0
R76 = CMP-0022651-4: RES, 90.9 k, 1%, 0.1 W, AEC-Q200 Grade 0, 0603; Manufacturer: Vishay-Dale; Power_W: 100mW; TempCo: 100 ppm/C; Value_Code: 90k9; Value: 90.9k; EIA_Code: E96; SizeY_mm: 0.8; SizeZ_mm: 1; Value2: 0.1W; SizeArea_mm2: 1.28; SizeX_mm: 1.6; AEC Qualified: Y; VDC_V: 75V; AEC Category: Q200; AEC Grade: 0
R80 = CMP-0023267-5: RES, 75.0 k, 1%, 0.1 W, 0603; Manufacturer: Yageo; Power_W: 100mW; TempCo: 100 ppm/C; Value_Code: 75k0; Value: 75.0k; EIA_Code: E96; Res_ohm: 75k; SizeX_mm: 1.6; SizeY_mm: 0.8; SizeZ_mm: 1; Value2: 0.1W; SizeArea_mm2: 1.28; AEC Qualified: N; VDC_V: 75V; AEC Category: Q200; SizeAreaWB_mm2: 4.68
R81 = CMP-0025792-4: RES, 390 k, 5%, 0.1 W, AEC-Q200 Grade 0, 0603; Manufacturer: Vishay-Dale; Power_W: 100mW; TempCo: 200 ppm/C; Value: 390k; EIA_Code: E24; SizeX_mm: 1.6; SizeY_mm: 0.8; SizeZ_mm: 1; Value2: 0.1W; SizeArea_mm2: 1.28; AEC Qualified: Y; VDC_V: 75V; AEC Category: Q200; AEC Grade: 0
R82 = CMP-0023142-5: RES, 49.9 k, 1%, 0.1 W, 0603; Manufacturer: Yageo; Power_W: 100mW; TempCo: 100 ppm/C; Value_Code: 49k9; Value: 49.9k; EIA_Code: E96; SizeX_mm: 1.6; SizeY_mm: 0.8; SizeZ_mm: 1; Value2: 0.1W; SizeArea_mm2: 1.28; AEC Qualified: N; VDC_V: 75V; AEC Category: Q200; SizeAreaWB_mm2: 4.68
R83 = CMP-0022692-3: RES, 22.0 k, 1%, 0.1 W, AEC-Q200 Grade 0, 0603; Manufacturer: Panasonic; Power_W: 100mW; TempCo: 100 ppm/C; Value_Code: 22k0; U/M: EA; Value: 22.0k; Res_ohm: 22k; SizeX_mm: 1.6; SizeY_mm: 0.8; SizeZ_mm: 1; Value2: 0.1W; SizeArea_mm2: 1.28; AEC Qualified: Y; VDC_V: 50V; AEC Grade: 0; AEC Category: Q200
R87 = CMP-0018647-3: RES, 2.7 M, 5%, 0.25 W, AEC-Q200 Grade 0, 1206; Manufacturer: Vishay-Dale; Power_W: 250mW; TempCo: 200 ppm/C; Value_Code: 2M70; Value: 2.7Meg; EIA_Code: E24; SizeX_mm: 3.2; SizeY_mm: 1.6; SizeZ_mm: 1.35; Value2: 0.25W; SizeArea_mm2: 5.12; AEC Qualified: Y; VDC_V: 200V; AEC Category: Q200; AEC Grade: 0
R88 = CMP-0022663-4: RES, 97.6 k, 1%, 0.1 W, AEC-Q200 Grade 0, 0603; Manufacturer: Vishay-Dale; Power_W: 100mW; TempCo: 100 ppm/C; Value_Code: 97k6; Value: 97.6k; EIA_Code: E96; SizeX_mm: 1.6; SizeY_mm: 0.8; SizeZ_mm: 1; Value2: 0.1W; SizeArea_mm2: 1.28; AEC Qualified: Y; VDC_V: 75V; AEC Category: Q200; AEC Grade: 0
R89 = CMP-0023292-5: RES, 82.0 k, 1%, 0.1 W, 0603; Manufacturer: Yageo; Power_W: 100mW; TempCo: 100 ppm/C; Value_Code: 82k0; Value: 82.0k; Res_ohm: 82k; SizeX_mm: 1.6; SizeY_mm: 0.8; SizeZ_mm: 1; Value2: 0.1W; SizeArea_mm2: 1.28; AEC Qualified: N; VDC_V: 75V; AEC Category: Q200; SizeAreaWB_mm2: 4.68
R90 = CMP-0022036-4: RES, 130 k, 1%, 0.1 W, AEC-Q200 Grade 0, 0603; Manufacturer: Vishay-Dale; Power_W: 100mW; TempCo: 100 ppm/C; Value: 130k; EIA_Code: E96; SizeX_mm: 1.6; SizeY_mm: 0.8; SizeZ_mm: 1; Value2: 0.1W; SizeArea_mm2: 1.28; AEC Qualified: Y; VDC_V: 75V; AEC Category: Q200; AEC Grade: 0
R91 = CMP-0015970-3: Manufacturer: Vishay-Dale; Power_W: 1W; TempCo: 200 ppm/C; Value1: 5%; Value: 47; EIA_Code: E24; SizeX_mm: 6.3; SizeY_mm: 3.2; SizeZ_mm: 0.71; SizeArea_mm2: 20.16; AEC Qualified: Y; VDC_V: 500V; AEC Grade: 0; AEC Category: Q200
RT1 = CMP-0002554-2: Thermistor NTC, 22 ohm, 20%, 15x7mm; Manufacturer: TDK; TaMax_C: 170°C; SizeX_mm: 15; SizeY_mm: 7.5; TaMin_C: -55°C; Power_W: 3.1W; SizeZ_mm: 47; SizeArea_mm2: 112.5; SizeAreaWB_mm2: 161.5; U/M: EA
RV1 = CMP-0002100-2: Varistor 275V RMS 10MM Radial, TH; PartNumber: 820512711; Manufacturer: Wuerth; SizeArea_mm2: 64.8; SizeAreaWB_mm2: 103.6; SizeX_mm: 12; SizeY_mm: 5.4; SizeZ_mm: 14.5
U1 U9 = CMP-0066947-1: 4A/4A Single Channel High-speed Low-side Gate Driver, DBV0005A (SOT-23-5); Alternate PartNumber: UCC27517DBVT; Alternate Manufacturer: Texas Instruments; Green_Lifecycle: Active; SizeAreaWB_mm2: 14.82; Green_REACh: Passed; U/M: EA; SizeZ_mm: 1.45; SizeX_mm: 2.8; SizeY_mm: 2.9; SizeArea_mm2: 8.12; CompType: IC
U3 = CMP-0065070-5: Natural Interleaving Transition Mode PFC Controller with Improved Light Load Efficiency, D0016A (SOIC-16); Alternate Manufacturer: Texas Instruments; SizeAreaWB_mm2: 95.2; U/M: EA; SizeZ_mm: 1.75; SizeX_mm: 6.0; SizeY_mm: 9.9; SizeArea_mm2: 59.4; CompType: IC
U13 = CMP-0073526-1: 36V, Low-Power, RRO, General-Purpose Operational Amplifier, DBV0005A (SOT-23-5); Alternate PartNumber: TLV171IDBVT; Alternate Manufacturer: Texas Instruments; SizeAreaWB_mm2: 14.82; U/M: EA; SizeZ_mm: 1.45; SizeX_mm: 2.8; SizeY_mm: 2.9; SizeArea_mm2: 8.12; CompType: IC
